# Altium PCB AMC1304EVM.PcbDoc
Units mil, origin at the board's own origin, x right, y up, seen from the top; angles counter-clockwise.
Board outline 2600 x 1425 mil, 2 copper layers (Top Layer, Bottom Layer), stack 62 mil thick; 29 components, 19 nets, 89 pads, 13 vias.
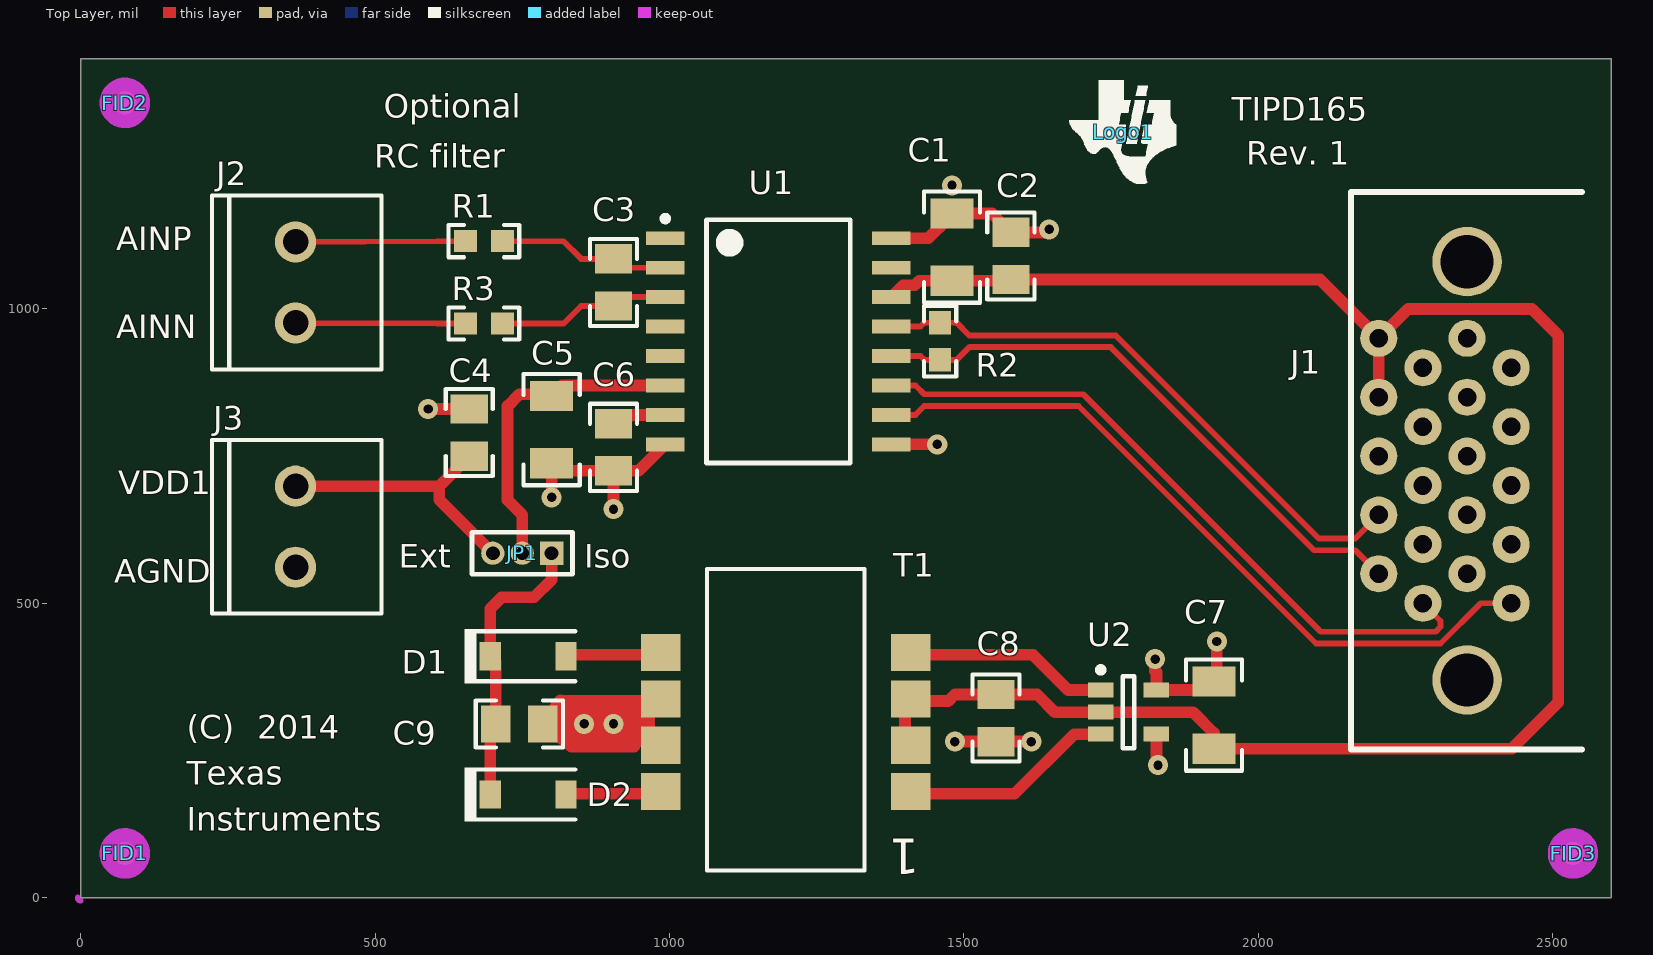
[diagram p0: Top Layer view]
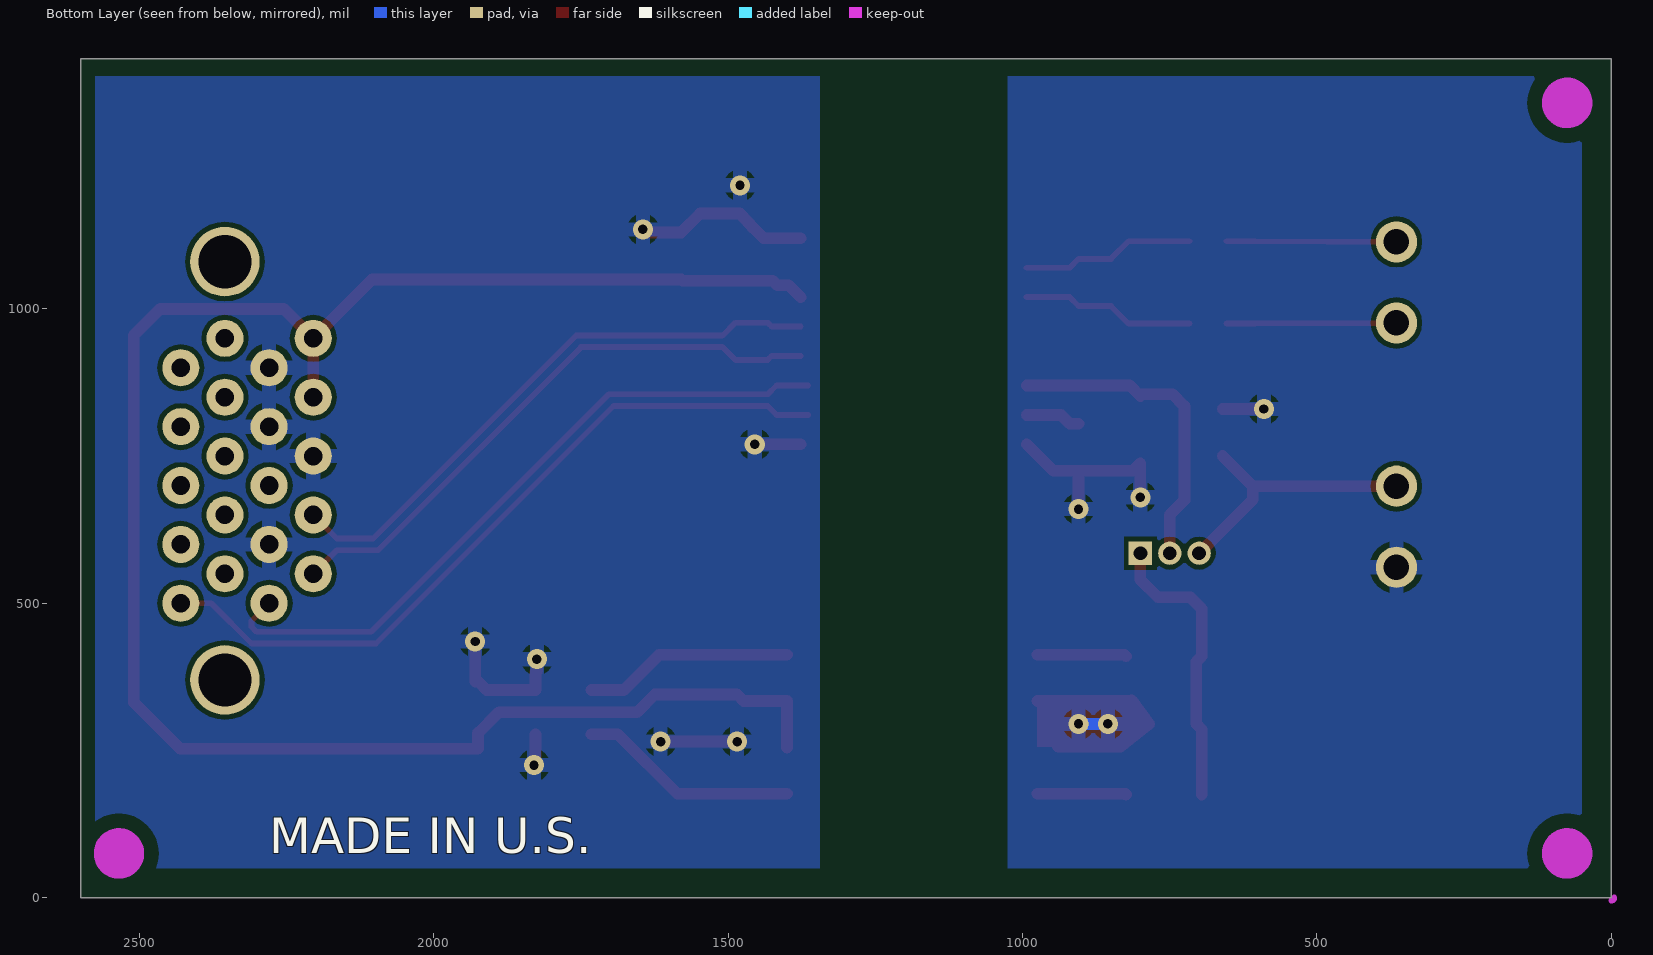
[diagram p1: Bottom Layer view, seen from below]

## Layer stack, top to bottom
Top Layer: signal copper 1.4
Dielectric: core 59.2, FR-4, Dk 4.8
Bottom Layer: signal copper 1.4

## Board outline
0,0 2600,0 2600,1425 0,1425

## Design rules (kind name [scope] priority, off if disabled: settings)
AcuteAngle [All] p1: minimum=4.50000000000000E+0001 checktracksonly=FALSE
AssemblyTestPointUsage [All] p1: valid=2
Clearance Clearance_BoardEdge_MountingHoles [OnCopper and InComponentClass('Mounting Holes') vs IsKeepOut] p1: gap=40
Clearance Clearance_BoardEdge_Poly [OnCopper and InPoly vs IsKeepOut] p2: gap=25
Clearance Clearance_BoardEdge [OnCopper and Not InComponentClass('Logo') and not InComponentClass('FiducialMark') and not InRegion(1000,500,4000,800) vs IsKeepOut] p3: gap=75
Clearance [All] p4: gap=8
ComponentClearance ComponentClearance_Logo [InComponentClass(Logo)] p1: gap=50 collisioncheckmode=3 verticalgap=10 showdistances=FALSE
ComponentClearance ComponentClearance_ScrewToNut [(HasFootprint('NY PMS 440 0025 PH')) vs (HasFootprint('Keystone_1902C'))] p2: gap=5 collisioncheckmode=3 verticalgap=10 showdistances=FALSE
ComponentClearance ComponentClearance_MountingHoles [InComponentClass('Mounting Holes')] p3: gap=250 collisioncheckmode=3 verticalgap=100000 showdistances=FALSE
ComponentClearance ComponentClearance_SmallPassives [HasFootprint('0201*') or HasFootprint('0402*') or HasFootprint('0508') or HasFootprint('0603*') or HasFootprint('0612') or HasFootprint('0805*') or HasFootprint('0815*') or HasFootprint('0830*') or HasFootprint('1206*') or HasFootprint('1210*') or HasFootprint('1808*') or HasFootprint('1812*') or HasFootprint('1825*') or HasFootprint('2010*') or HasFootprint('2220*') or HasFootprint('2225*') or HasFootprint('2512*') or HasFootprint('2728*') or HasFootprint('3518*') vs HasFootprint('0201*') or HasFootprint('0402*') or HasFootprint('0508') or HasFootprint('0603*') or HasFootprint('0612') or HasFootprint('0805*') or HasFootprint('0815*') or HasFootprint('0830*') or HasFootprint('1206*') or HasFootprint('1210*') or HasFootprint('1808*') or HasFootprint('1812*') or HasFootprint('1825*') or HasFootprint('2010*') or HasFootprint('2220*') or HasFootprint('2225*') or HasFootprint('2512*') or HasFootprint('2728*') or HasFootprint('3518*')] p4: gap=20 collisioncheckmode=3 verticalgap=10 showdistances=FALSE
ComponentClearance ComponentClearance_THtoSMT [IsThruComponent vs IsSMTComponent] p5: gap=100 collisioncheckmode=3 verticalgap=100000 showdistances=FALSE
ComponentClearance ComponentClearance_THtoTH [IsThruComponent vs IsThruComponent] p6: gap=118.11 collisioncheckmode=3 verticalgap=100000 showdistances=FALSE
ComponentClearance [All] p7: gap=40 collisioncheckmode=3 verticalgap=10 showdistances=FALSE
DiffPairsRouting [All] p1: maxlimit=100 minlimit=10 mostfreqgap=10 maxuncoupledlength=1000
FabricationTestPointUsage TestPointUsage [All] p1: valid=2 allowmultiple=FALSE
FabricationTestpoint Testpoint [All] p1: side=3 testpointundercomponent=TRUE minsize=40 maxsize=100 preferedsize=60 minholesize=0 maxholesize=40 preferedholesize=32 testpointgrid=1 allowsidetop=TRUE allowsidebottom=TRUE usegrid=TRUE gridtolerance=0.01
FanoutControl Fanout_LCC [IsLCC] p1: bgadir=Out bgaviamode=Centered fanoutstyle=Auto fanoutdirection=Alternating viagrid=1 // Fanout_LCC (Default Rule)
FanoutControl Fanout_BGA [IsBGA] p2: bgadir=Out bgaviamode=Centered fanoutstyle=Auto fanoutdirection=Alternating viagrid=1 // Fanout_BGA (Default Rule)
FanoutControl Fanout_Default [All] p4: bgadir=Out bgaviamode=Centered fanoutstyle=Auto fanoutdirection=Alternating viagrid=1 // Fanout_Default (Default Rule)
FanoutControl Fanout_Small [(CompPinCount < 5)] p5: bgadir=Out bgaviamode=Centered fanoutstyle=Auto fanoutdirection=OutThenIn viagrid=1 // Fanout_Small (Default Rule)
HoleSize [All] p1: absolutevalues=TRUE maxlimit=251 minlimit=8 maxpercent=80.000 minpercent=20.000
MinimumAnnularRing [All] p1: minimumring=9
MinimumSolderMaskSliver MinimumSolderMaskSliver_Logo [InComponentClass('Logo') vs InComponentClass('Logo')] p1: minsoldermaskwidth=0.7
MinimumSolderMaskSliver [All] p2: minsoldermaskwidth=4
PlaneConnect [All] p1: planeconnectstyle=Relief reliefexpansion=10 reliefentries=4 reliefconductorwidth=10 reliefairgap=10
PolygonConnect [All] p1: connectstyle=Relief reliefconductorwidth=25 reliefentries=4 polygonreliefangle="90 Angle" airgapwidth=10
RoutingVias [All] p1: holewidth=16 width=34 viastyle="Through Hole" minholewidth=8 minwidth=26 maxholewidth=40 maxwidth=65
SMDToCorner [All] p1: distance=30000
SilkToSilkClearance [All] p1: silktosilkclearance=5
SilkscreenOverComponentPads [All] p1: minsilkscreentomaskgap=5
SolderMaskExpansion [All] p1: expansion=6
Width Alimentacion_ANCHO_REGLA [InNetClass('Alimentacion_clase')] p1: maxlimit=100 minlimit=20 preferedwidth=20 checkconnectedcopper=TRUE
Width Width_1 [All] p2: maxlimit=20 minlimit=10 preferedwidth=10
14 further rules are at their usual default settings.

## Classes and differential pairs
component class AssemblyNote: ZZ1 ZZ2 ZZ3
component class FiducialMark: FID1 FID2 FID3
component class AMC1304_Hardware: FID1 FID2 FID3 SH-J1 ZZ1 ZZ2 ZZ3
component class Shunt: SH-J1
differential pair CLKIN: +CLKIN_P -CLKIN_N
differential pair DOUT: +DOUT_P -DOUT_N

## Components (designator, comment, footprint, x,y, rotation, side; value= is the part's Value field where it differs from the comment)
C1 "C3216C0G1E104J" 1206 1480,1105 r270 top
C2 "EMK212B7225KG-T" 0805_HV 1580,1090 r270 top
C3 "C2012C0G1E562J" 0805_HV 905,1045 r270 top
C4 "EMK212BJ106KG-T" 0805_HV 660,790 r90 top
C5 "C3216C0G1E104J" 1206 800,795 r270 top
C6 "C0805C475K8PACTU" 0805_HV 905,765 r270 top
C7 "C3216C0G1E104J" 1206 1925,310 r90 top
C8 "EMK212BJ106KG-T" 0805_HV 1555,305 r90 top
C9 "EMK212BJ106KG-T" 0805_HV 745,295 r180 top
D1 "MBR0520LT1G" SOD-123 760,410 r0 top
D2 "MBR0520LT1G" SOD-123 760,175 r0 top
FID1 "Fiducial" Fiducial10-20 75,75 r90 top
FID2 "Fiducial" Fiducial10-20 75,1350 r90 top
FID3 "Fiducial" Fiducial10-20 2535,75 r90 top
J1 "FX2-20S-1.27DS" FX2_20S_1P27_DS_RECEPT_GOOD 2355,1080.31 r270 top
J2 "1751248" CONN_1751248 365,1045 r270 top
J3 "1751248" CONN_1751248 365,630 r270 top
JP1 "GRPB031VWVN-RC" MHDR1X3 800,585 r180 top
Logo1 "Texas Instruments" TI_Symbol_Overlay_Small 1770,1300 r0 top
R1 "RT0603BRD0720RL" 0603 685,1115 r0 top
R2 "RT0603BRD0750R5L" 0603 1460,945 r90 top
R3 "RT0603BRD0720RL" 0603 685,975 r0 top
SH-J1 "M50-2000005" SNT-100-BK-G 3640,340 r90 top
T1 "DA2304-AL" DA230X_LAND_PATT 1410.2,180 r180 top
U1 "AMC1304" DW0016_HV_ISO_JAD 1185,945 r0 top
U2 "SN6501" DBV0005A_N 1780,315 r0 top
ZZ1 "These assemblies are ESD sensitive, ESD precautions shall be observed." AssemblyNote 3718,1061 r90 top
ZZ2 "These assemblies must be clean and free from flux and all contaminants. Use of no clean flux is not acceptable." AssemblyNote 3555,1125 r90 top
ZZ3 "These assemblies must comply with workmanship standards IPC-A-610 Class 2., unless otherwise specified." AssemblyNote 185,3652 r0 top

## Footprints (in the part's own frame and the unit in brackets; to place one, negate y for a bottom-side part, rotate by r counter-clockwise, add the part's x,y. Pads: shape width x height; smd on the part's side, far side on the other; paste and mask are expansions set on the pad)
0603 [mm] "0603 from SM-752 data"
  rect 1x0.95 smd: 1(-0.8,0) 2(0.8,0)
  silkscreen extent -1.52,-0.69 1.52,0.69, body extent -0.87,-0.47 0.87,0.47, height 0.85
0805_HV [mil] "0805 with 30mil clearance between pads"
  rect 50x63 smd: 1(-40,0) 2(40,0)
  silkscreen extent -74,-40 74,40, body extent -43,-29 43,29, height 43
1206 [mm] "1206 from SM-752 data"
  rect 1.3x1.85 smd: 1(-1.45,0) 2(1.45,0)
  silkscreen extent -2.4,-1.21 2.4,1.21, body extent -1.7,-0.9 1.7,0.9, height 1.35
AssemblyNote [mil] "Assembly Note"
CONN_1751248 [mil] "Phoenix Contact"
  round 70 hole 43.31: 1(-68.9,0) 2(68.9,0)
  silkscreen extent -148,-142 148,146, body extent -148,-142 148,146, height 335
DA230X_LAND_PATT [mm]
  rect 1.7x1.6 smd: 1(0,0) 2(0,-2) 3(0,-4) 4(0,-6) 5(10.8,-6) 6(10.8,-4) 7(10.8,-2) 8(10.8,0)
  silkscreen extent 2,-9.6 8.8,3.4
DBV0005A_N [mm] "SOT23, 5-Leads, Body 2.9x1.6mm, Pitch 0.95mm, Lead Span 2.8mm, IPC Medium Density"
  rect 1.1x0.65 smd: 1(-1.2,0.95) 2(-1.2,0) 3(-1.2,-0.95) 4(1.2,-0.95) 5(1.2,0.95)
  silkscreen extent -1.32,-1.55 0.25,1.95, body extent -0.87,-1.52 0.87,1.53, height 1.45
DW0016_HV_ISO_JAD [mm] "SOIC, 16-Leads, Body 10.5x7.6mm (max), Pitch 1.27mm, IPC High Density"
  rect 1.65x0.6 smd: 1(-4.875,4.445) 2(-4.875,3.175) 3(-4.875,1.905) 4(-4.875,0.635) 5(-4.875,-0.635) 6(-4.875,-1.905) 7(-4.875,-3.175) 8(-4.875,-4.445) 9(4.875,-4.445) 10(4.875,-3.175) 11(4.875,-1.905) 12(4.875,-0.635) 13(4.875,0.635) 14(4.875,1.905) 15(4.875,3.175) 16(4.875,4.445)
  silkscreen extent -5,-5.25 3.1,5.42, body extent -3.8,-5.25 3.8,5.25, height 2.65
Fiducial10-20 [mm]
  round 1 smd paste-0.5 mask+0.5: 1(0,0)
  Keep-Out Layer circle w1.178: c0,0 r0.5
FX2_20S_1P27_DS_RECEPT_GOOD [mm] "Hirose FX2-20P-1.27DS: CONN receptacle Right Angle 20POS 1.27MM."
  round 1.6 hole 0.8: a1(14.74,-1.905) a2(13.47,-3.81) a3(12.2,-1.905) a4(10.93,-3.81) a5(9.66,-1.905) a6(8.39,-3.81) a7(7.12,-1.905) a8(5.85,-3.81) a9(4.58,-1.905) a10(3.31,-3.81) b1(14.74,1.905) b2(13.47,0) b3(12.2,1.905) b4(10.93,0) b5(9.66,1.905) b6(8.39,0) b7(7.12,1.905) b8(5.85,0) b9(4.58,1.905) b10(3.31,0)
  round 3 hole 2.3: m0(18.05,0) m1(0,0)
  silkscreen extent -3,-5 21.05,4.95, body extent -2.35,-4.6 20.4,11.4, height 7.54
MHDR1X3 [mm] "Connector; Header; 3 Position"
  rect 1x1 hole 0.6: 1(0,0)
  round 1 hole 0.6: 2(1.27,0) 3(2.54,0)
  silkscreen extent -0.9,-0.9 3.44,0.9
SNT-100-BK-G [mil] "Samtec STEP model"
  body extent -100,-50 100,50, height 344
SOD-123 [mm] "On Semi recommended land pattern"
  rect 0.915x1.22 smd: 1(-1.637,0) 2(1.637,0)
  silkscreen extent -2.74,-1.17 2.03,1.17, body extent -1.93,-0.9 1.93,0.9, height 1.35
TI_Symbol_Overlay_Small [mil]
  silkscreen extent -90,-88 91,88

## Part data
C1 C5 C7: "CAP, CERM, 0.1uF, 25V, +/-5%, C0G/NP0, 1206"
C2: "CAP, CERM, 2.2uF, 16V, +/-10%, X7R, 0805"
C3: "CAP, CERM, 5600pF, 25V, +/-5%, C0G/NP0, 0805"
C4 C8 C9: "CAP, CERM, 10uF, 16V, +/-10%, X5R, 0805"
C6: "CAP, CERM, 4.7uF, 10V, +/-10%, X5R, 0805"
D1 D2: "Diode, Schottky, 20V, 0.5A, SOD-123"
FID1 FID2 FID3: "Fiducial mark.  There is nothing to buy or mount."
J1: library part FX2_20S_1p27_DS_recep_compon, "1.27mm Pitch Multi-function Two Piece Connector"
J2 J3: "Conn Term Block, 2POS, 3.5mm, TH"
JP1: library part MHDR1X3, "Header, 3-Pin"
Logo1: library part TI_Logo, "Texas Instrument Corporate Signature"
R1 R3: "RES, 20.0 ohm, 0.1%, 0.1W, 0603"
R2: "RES, 50.5 ohm, 0.1%, 0.1W, 0603"
SH-J1: library part 969102-0000-DA, "Shunt, 1.27 mm"
T1: library part DA2304-AL_JAD, "1:2.2 Isolation Transformer"
U1: library part AMC1304_JAD, "AMC1304Mx in 16-pin DW (SOIC) package"
U2: library part SN6501_JAD, "SN6501 transformer driver"
ZZ1 ZZ2 ZZ3: library part AssemblyNote

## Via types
v1: diameter 34, hole 16, Top Layer to Bottom Layer, 13 vias

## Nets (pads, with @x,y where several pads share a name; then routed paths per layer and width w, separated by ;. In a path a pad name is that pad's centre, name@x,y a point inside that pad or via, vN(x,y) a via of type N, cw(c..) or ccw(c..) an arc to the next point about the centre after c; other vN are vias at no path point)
CLKIN_N: J1.a2 R2.1 U1.12 | length 999.1
  Top Layer w10: U1.12 1426.5,920 1433,913.5 R2.1 1488,913.5 1509.5,935 1750,935 2095,590 2165,590 J1.a2
CLKIN_P: J1.a4 R2.2 U1.13 | length 999.1
  Top Layer w10: U1.13 1426.5,970 1433,976.5 R2.2 1488,976.5 1509.5,955 1758.28,955 2103.28,610 2165,610 J1.a4
DGND: C1.1 C2.1 C7.2 C8.1 J1.a3 J1.a6 J1.a7 J1.a9 U1.9 U1.16 U2.4 U2.5 | length 798.6
  Top Layer w20: U1.9 v1(1455,770) ; U1.16 1440,1120 1457.09,1137.09 C1.1 1547.91,1162.09 C2.1 1640,1130 v1(1645,1135) ; v1(1485,265) C8.1@1545,265 ; C8.1 C8.1@1545,265 ; v1(1615,265) C8.1@1545,265 ; v1(1825,405) 1825,385 1827.24,382.76 U2.5 1910.32,352.4 C7.2 ; U2.4 1827.24,227.76 v1(1830,225) ; C7.2@1930,367.09 v1(1930,435)
  other v1: 1480,1210
DOUT_N: J1.b1 U1.10 | length 1267.5
  Top Layer w10: U1.10@1364.13,820 U1.10 1418,820 1433,835 1695,835 2098.36,431.64 2309.93,431.64 2378.28,500 J1.b1
DOUT_P: J1.a1 U1.11 | length 1175
  Top Layer w10: U1.11@1364.13,870 U1.11 1418,870 1433,855 1703.28,855 2106.64,451.64 2301.64,451.64 2310,460 2310,470 J1.a1
DVDD: C1.2 C2.2 C7.1 C8.2 J1.a8 J1.a10 T1.2 T1.3 U1.14 U2.2 | length 3229.2
  Top Layer w20: U1.14 1397.12,1040.19 1416.87,1040.19 1424.59,1047.91 C1.2 1577.91,1047.91 C2.2 2105,1050 J1.a10 ; T1.2@1400.2,255 1400.2,333.74 1473.74,333.74 1485,345 C8.2 1625,345 1655,315 U2.2 1889.57,315 1925,279.57 C7.1 2431.34,252.91 2510,331.57 2510,955 2465,1000 2255,1000 J1.a10 ; J1.a8 J1.a10
GND: C4.2 C5.2 C6.2 C9.1 J3.2 T1.6 T1.7 U1.8 | length 948.8
  Top Layer w20: v1(590,830) C4.2 ; v1(800,680) C5.2 812.91,725 C6.2 ; v1(855,295) 816.26,333.74 ; v1(905,295) 940,260 940,256.26 833.74,256.26 C9.1 815,335 ; v1(905,660) C6.2 ; T1.6@975,333.74 816.26,333.74 ; U1.8 948.07,725 C6.2 ; 815,335 816.26,333.74 ; 815,335 816.26,333.74
  Bottom Layer w20: v1(855,295) v1(905,295)
LDO_INPUT_NET: C5.1 JP1.2 U1.6 | length 547
  Top Layer w20: JP1.2 750,650 725,675 725,835 745,855 C5.1@802.91,855 ; C5.1 817.91,870 U1.6
NetC3_1: C3.1 R1.2 U1.2 | length 295.2
  Top Layer w10: R1.2 820,1115 850,1085 C3.1 920,1070 U1.2
NetC3_2: C3.2 R3.2 U1.3 | length 295.2
  Top Layer w10: R3.2 820,975 850,1005 C3.2 920,1020 U1.3
NetC4_1: C4.1 J3.1 JP1.3 | length 467.8
  Top Layer w20: J3.1 608.9,698.9 ; C4.1 608.9,698.9 ; JP1.3 608.9,676.1 608.9,698.9
NetC6_1: C6.1 U1.7 | length 94.3
  Top Layer w20: C6.1 920,805 935,820 U1.7
NetC9_2: C9.2 D1.1 D2.1 JP1.1 | length 493.3
  Top Layer w20: D2.1 695.53,285.53 C9.2 705,400.53 D1.1 695.53,490.53 715,510 770,510 800,540 JP1.1
NetD1_2: D1.2 T1.5 | length 151.6
  Top Layer w20: D1.2 826.95,412.48 T1.5@975,412.48
NetD2_2: D2.2 T1.8 | length 151.1
  Top Layer w20: D2.2 825.73,176.26 T1.8@975,176.26
NetJ2_1: J2.1 R1.1 | length 288.5
  Top Layer w10: J2.1 605,1115 R1.1
NetJ2_2: J2.2 R3.1 | length 288.5
  Top Layer w10: J2.2 605,975 R3.1
NetT1_1: T1.1 U2.3 | length 374.5
  Top Layer w20: T1.1@1400.2,176.26 1586.26,176.26 1687.6,277.6 U2.3
NetT1_4: T1.4 U2.1 | length 357.4
  Top Layer w20: T1.4@1400.2,412.48 1617.52,412.48 1677.6,352.4 U2.1
pads on no net: FID1.1 FID2.1 FID3.1 J1.a5 J1.b2 J1.b3 J1.b4 J1.b5 J1.b6 J1.b7 J1.b8 J1.b9 J1.b10 J1.m0 J1.m1 U1.1 U1.4 U1.5 U1.15

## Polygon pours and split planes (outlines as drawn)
GND on Top Layer "Top Layer-No Net" (solid, pour order 4): 800,320 815,335 819,335
DGND on Bottom Layer "Bottom Layer-No Net" (solid, pour order 8): 1345,1395 1345,50 2575,50 2575,1395
GND on Bottom Layer "Bottom Layer-GND" (solid, pour order 3): 50,50 1025,50 1025,1395 50,1395

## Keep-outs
Keep-Out Layer:
  lines w10: -5,0 ccw(c0,0) 0,-5 ; -5,0 ccw(c0,0) 0,-5 ; -5,0 ccw(c0,0) 0,-5 ; -5,0 ccw(c0,0) 0,-5 ; -5,0 ccw(c0,0) 0,-5 ; -5,0 ccw(c0,0) 0,-5 ; -5,3450 cw(c0,3450) 0,3455 ; -5,3450 cw(c0,3450) 0,3455 ; -5,3450 cw(c0,3450) 0,3455 ; -5,3450 cw(c0,3450) 0,3455 ; -5,3450 cw(c0,3450) 0,3455 ; -5,3450 cw(c0,3450) 0,3455 ; 4950,3455 cw(c4950,3450) 4955,3450 ; 4950,3455 cw(c4950,3450) 4955,3450 ; 4950,3455 cw(c4950,3450) 4955,3450 ; 4950,3455 cw(c4950,3450) 4955,3450 ; 4950,3455 cw(c4950,3450) 4955,3450 ; 4950,3455 cw(c4950,3450) 4955,3450
  text ".Layer_Name" at 577,-858.49 h60

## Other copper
Top Layer:
  region net GND: 975,333.74 813.74,333.74 785,305 833.74,256.26 973.74,256.26 975,255
  text ".Layer_Name" at 577,-858.49 h60
Bottom Layer:
  text ".Layer_Name" at 577,-858.49 h60

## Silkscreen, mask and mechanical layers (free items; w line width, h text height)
Top Overlay:
  text "Optional" at 515,1325 h40
  text "TIPD165" at 1955,1320 h40
  text "Rev. 1" at 1980,1245 h40
  text "RC filter" at 498.34,1240 h40
  text "AINP" at 60,1100 h40
  text "AINN" at 60,950 h40
  text "VDD1" at 63.33,685 h40
  text "Ext" at 540,560 h40
  text "Iso" at 855,560 h40
  text "AGND" at 56.67,535 h40
  text "(C)" at 180,270 h40
  text "2014" at 300,270 h40
  text "Texas" at 180,191.67 h40
  text "Instruments" at 180,113.33 h40
  text ".Layer_Name" at 577,-858.49 h60
Bottom Overlay:
  text "MADE IN U.S." at 2280,75 h60
  text ".Layer_Name" at 577,-858.49 h60
Top Paste:
  text ".Layer_Name" at 577,-858.49 h60
Bottom Paste:
  text ".Layer_Name" at 577,-858.49 h60
Top Solder:
  text ".Layer_Name" at 577,-858.49 h60
  text ".Layer_Name" at 577,-858.49 h60
Bottom Solder:
  text ".Layer_Name" at 577,-858.49 h60
Drill Guide:
  text ".Layer_Name" at 577,-858.49 h60
M1 Board Outline:
  the board outline again, w10
  text ".Layer_Name" at 577,-858.49 h60
M2 Board Dimensions:
  rectangle: 124.5,-410.5 499.5,-285.5
  rectangle: -0.5,-285.5 124.5,-160.5
  lines w7: -0.5,-285.5 999.5,-285.5 ; 124.5,-410.5 124.5,-160.5 ; 249.5,-410.5 249.5,-160.5 ; 499.5,-410.5 499.5,-160.5 ; 749.5,-410.5 749.5,-160.5 ; -0.5,-410.5 -0.5,-160.5 999.5,-160.5 999.5,-223 999.5,-348 999.5,-410.5 -0.5,-410.5
  text "1000 (mil)" at -0.5,-465.5 h60
  text ".Layer_Name" at 577,-858.49 h60
M3 3D STEP Top:
  text ".Layer_Name" at 577,-858.49 h60
M4 3D STEP Bottom:
  text ".Layer_Name" at 577,-858.49 h60
M5 Assembly Top:
  lines w7: 7079,-229.5 8204,-229.5 ; 7079,-107 8201.5,-107 ; 7394,-349.5 7394,13 ; 7779,-349.5 7079,-349.5 ; 7779,13 7079,13 ; 7079,-349.5 7079,13 ; 7079,-349.5 8204,-349.5 8204,13 7079,13
  lines w10: -292,-930.17 6308,-930.17 ; -292,-726.83 6310,-726.83 ; -292,-523.5 -292,-1133.5 3713,-1133.5 6310,-1133.5 6310,-523.5 -291.5,-523.5 -291.5,-1133.5 1284,-1133.5 ; 2173,-1133.5 2173,-523.5 ; 3440,-726.83 3440,-523.5 ; 4280,-726.83 4280,-523.5 ; 4902,-1140 4902,-937.17
  text "TABLE 1" at 6930,-10 h40
  text "Label text" at 7539,-62 h40
  text "001" at 7171.5,-182 h40
  text "ChangeMe!" at 7449,-184.5 h40
  text "002" at 7171.5,-307 h40
  text "ChangeMe!" at 7444,-309.5 h40
  text "COMPONENTS MARKED 'DNP' SHOULD NOT BE POPULATED, AND MAY NOT BE IN BILL OF MATERIALS" at 1153.5,-318.5 h60
  text "Variant" at 6650,-320 h40
  text "ASSEMBLY VARIANT:" at 1153,-434 h60
  text ".VariantName" at 2189,-434 h60
  text "PCB VIEWED FROM TOP SIDE" at -228.5,-655.67 h60
  text "BOARD #:" at 2248,-655.67 h60
  text ".PRJ_Number" at 2793.5,-655.67 h60
  text "REV:" at 3638,-655.67 h60
  text ".PCB_Rev" at 3929.5,-655.67 h60
  text "SVN REV:" at 4476,-655.67 h60
  text ".VersionControl_RevNumber" at 4982,-655.67 h60
  text "IGNORE ->" at -228.5,-858.49 h60
  text "PLOT NAME =" at -228.5,-1064.34 h60
  text ".plot_File_Name" at 577,-1064.34 h60
  text "GENERATED    :" at 2250,-1064.34 h60
  text ".Print_Date" at 3119.5,-1064.34 h60
  text ".Print_Time" at 3848.5,-1064.34 h60
  text "TEXAS INSTRUMENTS" at 5113,-1064.34 h60
M6 Assembly Bottom:
  lines w10: -292.5,-727.33 6309.5,-727.33 ; -290.5,-930.67 6309.5,-930.67 ; 1115.5,-1140.5 1115.5,-937.67 ; 1737.5,-727.33 1737.5,-524 ; 2577.5,-727.33 2577.5,-524 ; 3844.5,-1134 3844.5,-524 ; 4733.5,-1134 6309,-1134 6309,-524 -292.5,-524 -292.5,-1134 2304.5,-1134 6309.5,-1134 6309.5,-524
  text "COMPONENTS MARKED 'DNP' SHOULD NOT BE POPULATED, AND MAY NOT BE IN BILL OF MATERIALS" at 6102,-318 h60
  text ".VariantName" at 5058,-434 h60
  text "ASSEMBLY VARIANT:" at 6097,-434 h60
  text ".VersionControl_RevNumber" at 1035.5,-656.17 h60
  text "SVN REV:" at 1541.5,-656.17 h60
  text ".PCB_Rev" at 2088,-656.17 h60
  text "REV:" at 2379.5,-656.17 h60
  text ".PRJ_Number" at 3224,-656.17 h60
  text "BOARD #:" at 3769.5,-656.17 h60
  text "PCB VIEWED FROM BOTTOM SIDE" at 6246,-656.17 h60
  text "IGNORE ->" at 2547.85,-858.49 h60
  text "TEXAS INSTRUMENTS" at 904.5,-1064.84 h60
  text ".Print_Time" at 2169,-1064.84 h60
  text ".Print_Date" at 2898,-1064.84 h60
  text "GENERATED    :" at 3767.5,-1064.84 h60
  text ".plot_File_Name" at 5440.5,-1064.84 h60
  text "PLOT NAME =" at 6246,-1064.84 h60
M9 Title Sheet:
  drawing of 57 lines, arcs and shapes, not listed
  text "1" at 739.84,8036.5 h70
  text "2" at 3235.5,8036.5 h70
  text "3" at 5724.84,8036.5 h70
  text "4" at 8231.51,8036.5 h70
  text "5" at 10730.5,8036.5 h70
  text "6" at 13235.5,8036.5 h70
  text "A" at -416.5,6893.5 h70
  text "A" at 14383.5,6893.5 h70
  text "B" at -416.5,4513.5 h70
  text "B" at 14383.5,4513.5 h70
  text "C" at -416.5,2138.5 h70
  text "C" at 14383.5,2138.5 h70
  text "PROJECT TITLE:" at 11343.5,277.5 h45
  text ".PRJ_Title" at 11393.5,144.17 h70
  text "DESIGNED FOR:" at 11343.5,-23.5 h45
  text ".PRJ_Customer" at 11393.5,-163.5 h70
  text "D" at -416.5,-231.5 h70
  text "D" at 14383.5,-231.5 h70
  text "FILE NAME:" at 11343.5,-323.5 h45
  text ".PCB_File_Name_No_Path" at 11393.5,-443.5 h70
  text "Texas Instruments (TI) and/or its licensors do not warrant the accuracy or completeness of this specification" at 6374,-605.34 h45
  text "ENGINEER:" at 11343.5,-613.5 h45
  text "LAYOUT BY:" at 12848.5,-613.5 h45
  text "or any information contained therein. TI and/or its licensors do not warrant that this design will meet" at 6329.01,-718 h45
  text ".PRJ_Engineer" at 11393.5,-768.49 h70
  text ".PCB_Layout" at 12899,-768.49 h70
  text "the specifications, will be suitable for your application or fit for any particular purpose, or will operate in" at 6329.01,-830.67 h45
  text ".Layer_Name" at 577,-858.49 h60
  text "ALTIUM DESIGNER VERSION:" at 12848.5,-923.5 h45
  text "an implementation. TI and/or its licensors do not warrant that the design is production worthy. You should" at 6329.01,-943.33 h45
  text "completely validate and test your design implementation to confirm the system functionality for your application." at 6374,-1056 h45
  text ".print_Scale" at 11393.5,-1056.83 h70
  text ".Application_BuildNumber" at 12899,-1056.83 h70
  text "1" at 739.84,-1263.5 h70
  text "2" at 3235.5,-1263.5 h70
  text "3" at 5724.84,-1263.5 h70
  text "4" at 8231.51,-1263.5 h70
  text "5" at 10730.5,-1263.5 h70
  text "6" at 13235.5,-1263.5 h70
M10 Fab Notes:
  drawing of 203 lines, arcs and shapes, not listed
  text "DESIGN INFORMATION" at 12381.02,6810 h60
  text "(REFER ALSO ARRAY/PANEL PROFILING INFORMATION)" at 12019.46,6648.29 h60
  text "BOARD SIZE" at 11333.46,6644 h60
  text "2600MIL" at 11795.78,6516.18 h60
  text "X" at 12301.46,6516.18 h60
  text "1425MIL" at 12532.78,6516.18 h60
  text "Number of Layers :" at 11736.46,6319 h60
  text "2" at 12831.27,6309 h60
  text "MIN. TRACK WIDTH:" at 11736.46,6180 h60
  text "8" at 12832.7,6180 h60
  text "MIL" at 12987.46,6180 h60
  text "MIN. CLEARANCE:" at 11736.46,6048 h60
  text "8" at 12832.7,6048 h60
  text "MIL" at 12987.46,6048 h60
  text "MIN. VIA PAD SIZE:" at 11736.46,5916 h60
  text "24" at 12802.71,5916 h60
  text "MIL" at 12987.46,5916 h60
  text "0.05mm (2MIL)" at 12431.46,5774.29 h60
  text "MINIMUM ANNULAR RING" at 11407.23,5770 h60
  text "EXTERNAL" at 13139.46,5770 h60
  text "PER" at 11607.23,5652 h60
  text "IPC-D-275 CLASS 2 LEVEL C" at 11827.23,5652 h60
  text "MIL, HOLES" at 13315.46,5539.71 h60
  text "+/-" at 12923,5539 h60
  text "+/-" at 13777,5539 h60
  text "REGISTRATION TOLERANCES:" at 11407.23,5534 h60
  text "METAL" at 12607,5534 h60
  text "5" at 13183.2,5534 h60
  text "3" at 14016.2,5534 h60
  text "MIL" at 14132.46,5534 h60
  text "MATERIAL:" at 11332.46,5324.54 h60
  text "X" at 11610,5190 h60
  text "FR-4 High Tg" at 12318.9,5184.21 h60
  text "FR-4" at 11793.46,5175.64 h60
  text "OTHER" at 13241.46,5175.64 h60
  text "62 MIL (1.6mm) +/-10%" at 12073.56,5012.92 h60
  text "THICKNESS:" at 11407.23,5008.64 h60
  text "X" at 11945.4,5008.64 h60
  text "OTHER" at 13358.46,5008.64 h60
  text "TOLERANCE:" at 11407.23,4850.64 h60
  text "X" at 12246.53,4850.64 h60
  text "ANSI IPC-6012 TYPE 3 CLASS 2" at 12433.48,4850.64 h60
  text "OTHER +/-" at 12433.46,4694.64 h60
  text "BOW & TWIST:" at 11407.23,4537.64 h60
  text "X" at 12246.53,4537.64 h60
  text "ANSI IPC-6012 TYPE 3 CLASS 2" at 12433.48,4537.64 h60
  text "OTHER +/-" at 12433.46,4379.13 h60
  text "COPPER THICKNESS (FINISHED):" at 11332.46,4243.64 h60
  text "1.4MIL (1oz)" at 12212.46,4090.92 h60
  text "2MIL (1.4oz)" at 12979.46,4090.92 h60
  text "2.8MIL (2oz)" at 13706.46,4090.92 h60
  text "OUTER:" at 11689.46,4086.64 h60
  text "X" at 12084,4086 h60
  text "1.4MIL (1oz)" at 12562.46,3933.92 h60
  text "2.8MIL (2oz)" at 13406.46,3933.92 h60
  text "INNER SIGNAL:" at 11689.46,3929.64 h60
  text "X" at 12435.42,3929.64 h60
  text "DRILLING:" at 11332.46,3790.64 h60
  text "REFERENCE:" at 11407.23,3673.64 h60
  text "X" at 12055.46,3673.64 h60
  text "AS SHOWN" at 12242.46,3673.64 h60
  text "X" at 12956.46,3673.64 h60
  text "NC_DRILL FILES" at 13093.46,3673.64 h60
  text "PTH MIN COPPER THICKNESS:" at 11407.23,3515.64 h60
  text "X" at 12757.46,3515.64 h60
  text "1MIL" at 12894.46,3515.64 h60
  text "OTHER" at 13391.46,3515.64 h60
  text "BOARD FINISH:" at 11332.46,3356.64 h60
  text "SILKSCREEN:" at 11487.68,3238.64 h60
  text "X" at 12436.46,3238.64 h60
  text "TOP" at 12562.46,3238.64 h60
  text "X" at 12946.46,3238.64 h60
  text "BOTTOM" at 13073.46,3238.64 h60
  text "SILKSCREEN COLOR:" at 11487.68,3071.64 h60
  text "X" at 12435.42,3071.64 h60
  text "WHITE" at 12562.46,3071.64 h60
  text "OTHER" at 13073.46,3071.64 h60
  text "SOLDER RESIST COLOR:" at 11487.68,2901.64 h60
  text "X" at 12055.42,2742.44 h60
  text "GREEN" at 12182.46,2742.44 h60
  text "BLUE" at 12773.46,2742.44 h60
  text "OTHER" at 13311.46,2742.44 h60
  text "X" at 13495,2560 h60
  text "IMMERSION GOLD (ENIG)" at 12393.46,2553.92 h60
  text "SURFACE FINISH:" at 11332.46,2549.64 h60
  text "Pb-FREE HASL" at 13625.75,2549.64 h60
  text "OTHER" at 12393.46,2392.64 h60
  text "ARRAY/PANEL:" at 11332.46,2213.64 h60
  text "CUT AND TRIM PER MECH LAYER 1" at 12393.46,2209.35 h60
  text "N.C. ROUTE" at 12393.46,2057.64 h60
  text "X" at 13072.46,2057.64 h60
  text "V. SCORE" at 13259.46,2057.64 h60
  text "CERTIFICATION:" at 11332.46,1920.64 h60
  text "MATERIALS AND WORKMANSHIP FOR ALL PCBS" at 12057.46,1920.64 h60
  text "TO MEET OR EXCEED THE REQUIREMENTS OF:" at 12057.46,1822.64 h60
  text "X" at 11683.96,1686.13 h60
  text "ANSI IPC-A-600F CLASS ->" at 11822.96,1686.13 h60
  text "X" at 13462.02,1686.13 h60
  text "2" at 13580.96,1686.14 h60
  text "1" at 13265.96,1684.64 h60
  text "3" at 13934.96,1684.64 h60
  text "X" at 11686.02,1526.64 h60
  text "UL 94V-0" at 11822.96,1526.64 h60
  text "X" at 12498.02,1526.64 h60
  text "RoHS" at 12634.96,1526.64 h60
  text "OTHER" at 13279.36,1526.64 h60
  text "PER ORDER" at 13676.42,1526.64 h60
  text "ADDITIONAL REQUIREMENTS:" at 11332.46,1385.64 h60
  text "MICROSECTION:" at 11407.23,1270.64 h60
  text "YES" at 12312.96,1270.64 h60
  text "REQUIRED" at 13174.46,1114.49 h60
  text "BARE BOARD ELEC. TEST:" at 11407.23,1111.64 h60
  text "NONE" at 12712.96,1111.64 h60
  text "X" at 13047.46,1111.64 h60
  text "PER ORDER" at 13766.46,1111.64 h60
  text "MANUFACTURER'S ID/LOGO:" at 11407.23,954.64 h60
  text "RAIL" at 12872.96,950.35 h60
  text "X" at 13247.46,950.35 h60
  text "METAL" at 13364.77,950.35 h60
  text "SILK" at 13876.46,950.35 h60
  text ".Layer_Name" at 577,-858.49 h60
M11 Gerber Information:
  lines w10: -292,-930.17 6308,-930.17 ; -292,-726.83 6310,-726.83 ; -292,-523.5 -292,-1133.5 3713,-1133.5 6310,-1133.5 6310,-523.5 -291.5,-523.5 -291.5,-1133.5 1284,-1133.5 ; 2173,-1133.5 2173,-523.5 ; 3440,-726.83 3440,-523.5 ; 4280,-726.83 4280,-523.5 ; 4902,-1140 4902,-937.17
  text "ALL ARTWORK VIEWED FROM TOP SIDE" at -228.5,-655.67 h60
  text "BOARD #:" at 2248,-655.67 h60
  text ".PRJ_Number" at 2793.5,-655.67 h60
  text "REV:" at 3638,-655.67 h60
  text ".PCB_Rev" at 3929.5,-655.67 h60
  text "SVN REV:" at 4476,-655.67 h60
  text ".VersionControl_RevNumber" at 4982,-655.67 h60
  text "LAYER NAME =" at -228.5,-858.49 h60
  text "PLOT NAME =" at -228.5,-1064.34 h60
  text ".plot_File_Name" at 577,-1064.34 h60
  text "GENERATED    :" at 2250,-1064.34 h60
  text ".Print_Date" at 3119.5,-1064.34 h60
  text ".Print_Time" at 3848.5,-1064.34 h60
  text "TEXAS INSTRUMENTS" at 5113,-1064.34 h60
M12 Stackup:
  lines w6: 11360,7460 13910,7460 ; 11360,7564.4 13910,7564.4 ; 11300,6975 ccw(c11334,6975) 11334,6941 13936,6941 ccw(c13936,6975) 13970,6975 13970,7681 ccw(c13936,7681) 13936,7715 11334,7715 ccw(c11334,7681) 11300,7681 11300,6975
  text "The Stackup Legend below this is static." at 11605.5,7874.5 h60
  text "If you change the stackup, update the Legend." at 11615.5,7784.5 h60
  text "Layer Stack Up Detail for: Ref_Design.PcbDoc" at 11360,7597.1 h57
  text "Layer" at 11360,7525.4 h24
  text "Gerber" at 12255.81,7525.4 h24
  text "Copper" at 12819.33,7525.4 h24
  text "Dielectric" at 13422.04,7525.4 h24
  text "Name" at 11360,7477.4 h24
  text "Document" at 12255.81,7477.4 h24
  text "Thickness" at 12819.33,7477.4 h24
  text "Material" at 13422.04,7477.4 h24
  text "Top Solder Mask" at 11360,7384.44 h34
  text "(.GTS)" at 12255.81,7384.44 h34
  text "Solder Resist" at 13422.04,7384.44 h34
  text "Top Layer" at 11360,7287.69 h34
  text "(.GTL)" at 12255.81,7287.69 h34
  text "1.4mil" at 12819.33,7287.69 h34
  text "FR-4" at 13422.04,7239.31 h34
  text "Bottom Layer" at 11360,7190.94 h34
  text "(.GBL)" at 12255.81,7190.94 h34
  text "1.4mil" at 12819.33,7190.94 h34
  text "Bottom Solder Mask" at 11360,7094.19 h34
  text "(.GBS)" at 12255.81,7094.19 h34
  text "Solder Resist" at 13422.04,7094.19 h34
  text ".Layer_Name" at 577,-858.49 h60
M13 Component Bodies Top:
  text ".Layer_Name" at 577,-858.49 h60
M14 Component Bodies Bottom:
  text ".Layer_Name" at 577,-858.49 h60
M15 Courtyards Top:
  text ".Layer_Name" at 577,-858.49 h60
M16 Courtyards Bottom:
  text ".Layer_Name" at 577,-858.49 h60
Drill Drawing:
  text ".legend" at 5790,3090 h60
  text "Drill Table" at 5810,2870 h60
  text ".LEGEND" at 5515,1855 h60
  text ".Layer_Name" at 577,-858.49 h60

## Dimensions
0,0 to 2600,0 on M2 Board Dimensions
0,0 to 0,1425 on M2 Board Dimensions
